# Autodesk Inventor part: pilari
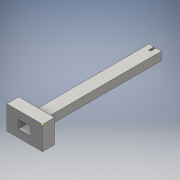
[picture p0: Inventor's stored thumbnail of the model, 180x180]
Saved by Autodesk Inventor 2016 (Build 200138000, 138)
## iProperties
Created: 2016-02
Part Number: pilari
Material: Generic
Document SubType Name: Modeling
Designer: Juha-Pekka
Density: 1 g/cm^3
Appearance: Default
Author: Juha-Pekka
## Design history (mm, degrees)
sketch "Sketch1"
  geometry: L1 (0, 0)-(30, 0); L2 (30, 0)-(30, -20); L3 (30, -20)-(0, -20); L4 (0, -20)-(0, 0); L5 (20.238, -6.508)-(9.762, -6.508); L6 (9.762, -6.508)-(9.762, -13.492); L7 (9.762, -13.492)-(20.238, -13.492); L8 (20.238, -13.492)-(20.238, -6.508); L9 (20.238, -6.508)-(9.762, -13.492); L10 (9.762, -6.508)-(20.238, -13.492); 1 further point
  constraints: 20 end point, 4 parallel, 2 horizontal, 2 midpoint, 2 perpendicular
  dimensions: "d0" = 30 distance of L2.end L3.end; "d1" = 20 distance of L1.end L2.end
extrude "Extrusion1" new body sketch "Sketch1" distance "d2" = 10; taper "d3" = 0 deg
sketch "Sketch2"
  geometry: L1 (-9.762, 6.508)-(-20.238, 6.508) reference; L2 (-20.238, 13.492)-(-9.762, 13.492) reference; L3 (-20.238, 6.508)-(-9.762, 6.508); L4 (-9.762, 6.508)-(-9.762, 13.492); L5 (-9.762, 13.492)-(-20.238, 13.492); L6 (-20.238, 13.492)-(-20.238, 6.508); 1 further point
  constraints: 8 end point, 2 parallel, 1 horizontal, 1 perpendicular
extrude "Extrusion2" join sketch "Sketch2" distance "d4" = 100; taper "d5" = 0 deg
sketch "Sketch3"
  geometry: 1 further point
sketch "Sketch4"
  geometry: L1 (10.475, 100)-(0, 100) reference; L2 (4.252, 100)-(6.022, 100); L3 (6.022, 100)-(6.022, 95.333); L4 (6.022, 95.333)-(4.252, 95.333); L5 (4.252, 95.333)-(4.252, 100); 1 further point
  constraints: 8 end point, 2 parallel, 1 horizontal, 1 perpendicular, 1 point on line
extrude "Extrusion3" cut sketch "Sketch4" distance "d6" = 10; taper "d7" = 0 deg
body "Solid1"
